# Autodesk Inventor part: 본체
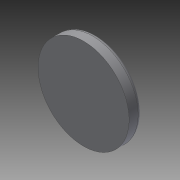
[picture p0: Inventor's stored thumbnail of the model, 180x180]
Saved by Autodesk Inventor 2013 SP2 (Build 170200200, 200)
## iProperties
Created: 2024-08
Part Number: 본체
Material: Generic
Document SubType Name: Modeling
Designer: a
Density: 1 g/cm^3
Author: a
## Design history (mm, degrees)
sketch "스케치1"
  geometry: C1 r 71 at (0, 0); 1 further point
  constraints: 1 centre point, 1 coincident
  dimensions: "d0" = 142 diameter of C1
extrude "돌출1" new body sketch "스케치1" distance "d2" = 20; taper "d3" = 0 deg
fillet "모깎기1" dims "d4" = 6
node "솔리드1"
